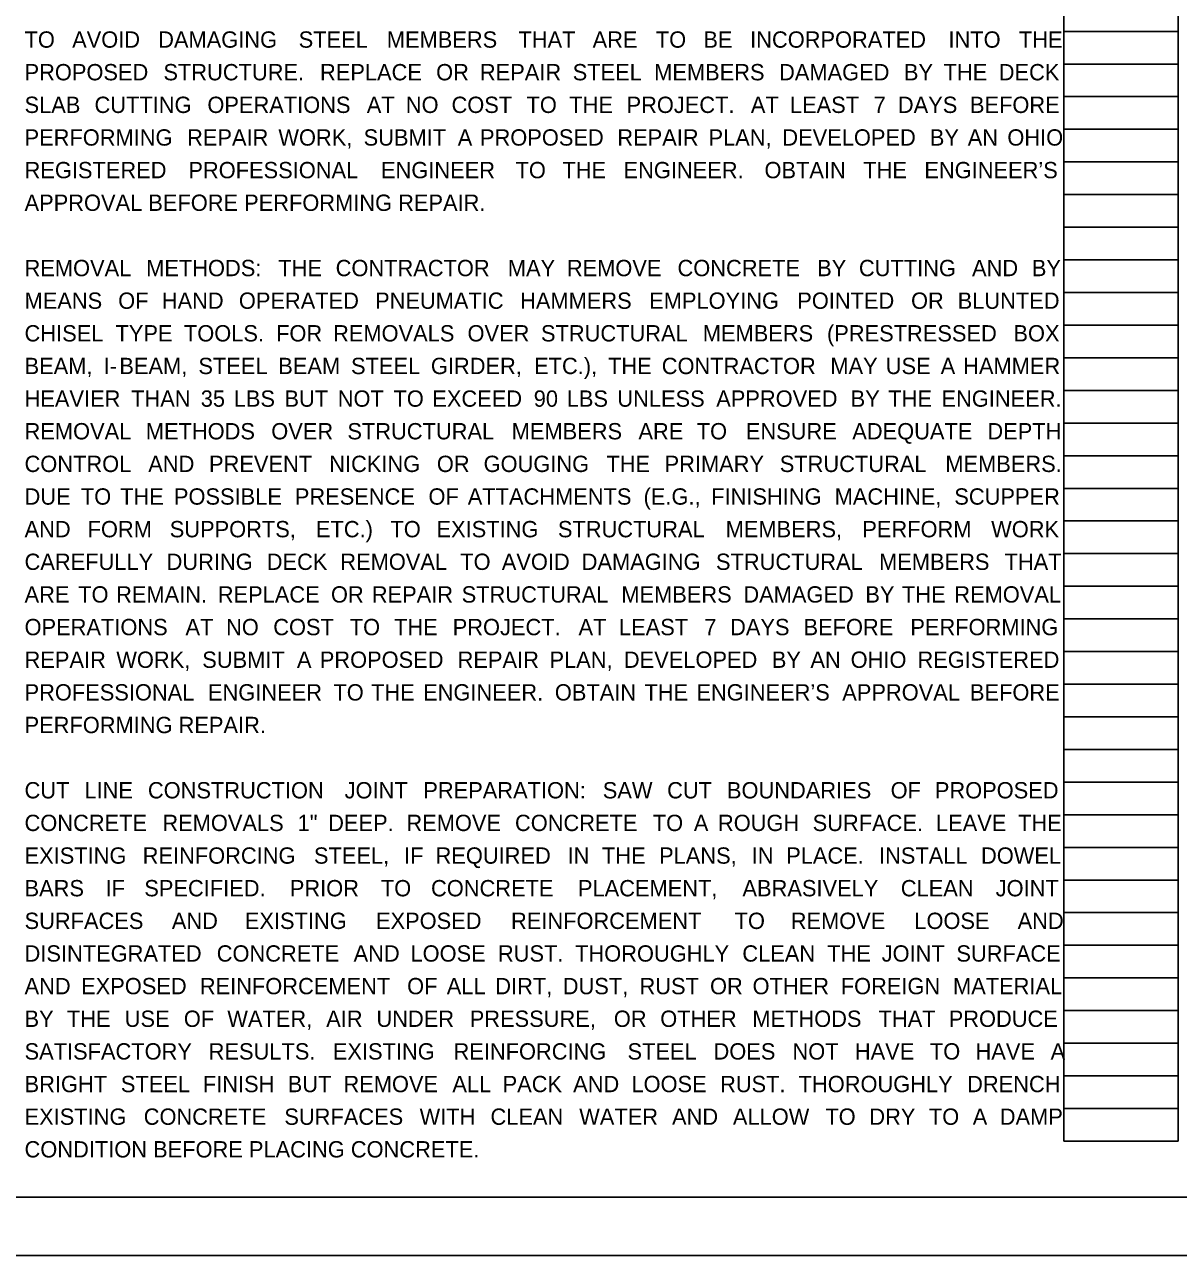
# Model space of a CAD drawing. Extents: x 0 to 34, y 0 to 22.
# Drawn here: x 12.29 to 22.19, y 0 to 10.56 of the extents above; entities that cross this region are included whole.
import ezdxf

# ---------------------------------------------------------------- set-up
doc = ezdxf.new("R2010")
doc.units = 0
for name, color, linetype in [('SC_Scratch1', 7, 'Continuous'), ('SH_Border', 7, 'Continuous'), ('SH_Cut_Line', 7, 'Continuous'), ('SH_Text', 7, 'Continuous')]:
    doc.layers.add(name, color=color, linetype=linetype)

msp = doc.modelspace()

# ---------------------------------------------------------------- linework, layer by layer
at = {"layer": 'SC_Scratch1'}
for p, q in [((21.207, 0.98), (21.207, 21.14)), ((22.187, 0.98), (22.187, 21.14)), ((21.207, 10.5), (22.187, 10.5)), ((21.207, 10.22), (22.187, 10.22)), ((21.207, 9.94), (22.187, 9.94)), ((21.207, 9.66), (22.187, 9.66)), ((21.207, 9.38), (22.187, 9.38)), ((21.207, 9.1), (22.187, 9.1)), ((21.207, 8.82), (22.187, 8.82)), ((21.207, 8.54), (22.187, 8.54)), ((21.207, 8.26), (22.187, 8.26)), ((21.207, 7.98), (22.187, 7.98)), ((21.207, 7.7), (22.187, 7.7)), ((21.207, 7.42), (22.187, 7.42)), ((21.207, 7.14), (22.187, 7.14)), ((21.207, 6.86), (22.187, 6.86)), ((21.207, 6.58), (22.187, 6.58)), ((21.207, 6.3), (22.187, 6.3)), ((21.207, 6.02), (22.187, 6.02)), ((21.207, 5.74), (22.187, 5.74)), ((21.207, 5.46), (22.187, 5.46)), ((21.207, 5.18), (22.187, 5.18)), ((21.207, 4.9), (22.187, 4.9)), ((21.207, 4.62), (22.187, 4.62)), ((21.207, 4.34), (22.187, 4.34)), ((21.207, 4.06), (22.187, 4.06)), ((21.207, 3.78), (22.187, 3.78)), ((21.207, 3.5), (22.187, 3.5)), ((21.207, 3.22), (22.187, 3.22)), ((21.207, 2.94), (22.187, 2.94)), ((21.207, 2.66), (22.187, 2.66)), ((21.207, 2.38), (22.187, 2.38)), ((21.207, 2.1), (22.187, 2.1)), ((21.207, 1.82), (22.187, 1.82)), ((21.207, 1.54), (22.187, 1.54)), ((21.207, 1.26), (22.187, 1.26)), ((21.207, 0.98), (22.187, 0.98))]:
    msp.add_line(p, q, dxfattribs=at)
msp.add_lwpolyline([(0, 22), (34, 22), (34, 0), (0, 0)], close=True, dxfattribs=at)
at = {"layer": 'SH_Border'}
msp.add_lwpolyline([(1.5, 21.5), (33.5, 21.5), (33.5, 0.5), (1.5, 0.5)], close=True, dxfattribs=at)
at = {"layer": 'SH_Cut_Line'}
msp.add_lwpolyline([(0, 0), (34, 0), (34, 22), (0, 22)], close=True, dxfattribs=at)

# ---------------------------------------------------------------- texts
at = {"layer": 'SH_Text'}
for s, p in [('TO ', (12.293, 10.36)), ('AVOID ', (12.701, 10.36)), ('DAMAGING ', (13.439, 10.36)), ('STEEL ', (14.644, 10.36)), ('MEMBERS ', (15.4, 10.36)), ('THAT ', (16.529, 10.36)), ('ARE ', (17.165, 10.36)), ('TO ', (17.707, 10.36)), ('BE ', (18.115, 10.36)), ('INCORPORATED ', (18.516, 10.36)), ('INTO ', (20.217, 10.36)), ('THE ', (20.821, 10.36)), ('PROPOSED ', (12.293, 10.08)), ('STRUCTURE. ', (13.484, 10.08)), ('REPLACE ', (14.827, 10.08)), ('OR ', (15.823, 10.08)), ('REPAIR ', (16.198, 10.08)), ('STEEL ', (16.994, 10.08)), ('MEMBERS ', (17.693, 10.08)), ('DAMAGED ', (18.764, 10.08)), ('BY ', (19.835, 10.08)), ('THE ', (20.175, 10.08)), ('DECK ', (20.648, 10.08)), ('SLAB ', (12.293, 9.8)), ('CUTTING ', (12.893, 9.8)), ('OPERATIONS ', (13.861, 9.8)), ('AT ', (15.228, 9.8)), ('NO ', (15.563, 9.8)), ('COST ', (15.955, 9.8)), ('TO ', (16.598, 9.8)), ('THE ', (16.965, 9.8)), ('PROJECT. ', (17.456, 9.8)), ('AT ', (18.522, 9.8)), ('LEAST ', (18.857, 9.8)), ('7 ', (19.575, 9.8)), ('DAYS ', (19.783, 9.8)), ('BEFORE ', (20.401, 9.8)), ('PERFORMING ', (12.293, 9.52)), ('REPAIR ', (13.687, 9.52)), ('WORK, ', (14.47, 9.52)), ('SUBMIT ', (15.201, 9.52)), ('A ', (16.008, 9.52)), ('PROPOSED ', (16.199, 9.52)), ('REPAIR ', (17.377, 9.52)), ('PLAN, ', (18.159, 9.52)), ('DEVELOPED ', (18.792, 9.52)), ('BY ', (20.057, 9.52)), ('AN ', (20.382, 9.52)), ('OHIO ', (20.722, 9.52)), ('REGISTERED ', (12.293, 9.24)), ('PROFESSIONAL ', (13.698, 9.24)), ('ENGINEER ', (15.35, 9.24)), ('TO ', (16.504, 9.24)), ('THE ', (16.906, 9.24)), ('ENGINEER. ', (17.43, 9.24)), ('OBTAIN ', (18.639, 9.24)), ('THE ', (19.486, 9.24)), ('ENGINEER’S ', (20.01, 9.24)), ('APPROVAL BEFORE PERFORMING REPAIR. ', (12.293, 8.96)), ('REMOVAL ', (12.293, 8.4)), ('METHODS: ', (13.336, 8.4)), ('THE ', (14.469, 8.4)), ('CONTRACTOR ', (14.961, 8.4)), ('MAY ', (16.438, 8.4)), ('REMOVE ', (16.944, 8.4)), ('CONCRETE ', (17.893, 8.4)), ('BY ', (19.091, 8.4)), ('CUTTING ', (19.449, 8.4)), ('AND ', (20.419, 8.4)), ('BY ', (20.932, 8.4)), ('MEANS ', (12.293, 8.12)), ('OF ', (13.096, 8.12)), ('HAND ', (13.47, 8.12)), ('OPERATED ', (14.131, 8.12)), ('PNEUMATIC ', (15.299, 8.12)), ('HAMMERS ', (16.543, 8.12)), ('EMPLOYING ', (17.65, 8.12)), ('POINTED ', (18.92, 8.12)), ('OR ', (19.896, 8.12)), ('BLUNTED ', (20.296, 8.12)), ('CHISEL ', (12.293, 7.84)), ('TYPE ', (13.073, 7.84)), ('TOOLS. ', (13.66, 7.84)), ('FOR ', (14.45, 7.84)), ('REMOVALS ', (14.939, 7.84)), ('OVER ', (16.092, 7.84)), ('STRUCTURAL ', (16.722, 7.84)), ('MEMBERS ', (18.11, 7.84)), ('(PRESTRESSED ', (19.175, 7.84)), ('BOX ', (20.774, 7.84)), ('ETC.), ', (16.663, 7.56)), ('BEAM, ', (12.293, 7.56)), ('I-', (12.971, 7.56)), ('BEAM, ', (13.106, 7.56)), ('STEEL ', (13.784, 7.56)), ('BEAM ', (14.469, 7.56)), ('STEEL ', (15.093, 7.56)), ('GIRDER, ', (15.778, 7.56)), ('THE ', (17.297, 7.56)), ('CONTRACTOR ', (17.758, 7.56)), ('MAY ', (19.204, 7.56)), ('USE ', (19.679, 7.56)), ('A ', (20.15, 7.56)), ('HAMMER ', (20.343, 7.56)), ('HEAVIER ', (12.293, 7.28)), ('THAN ', (13.207, 7.28)), ('35 ', (13.804, 7.28)), ('LBS ', (14.087, 7.28)), ('BUT ', (14.522, 7.28)), ('NOT ', (14.979, 7.28)), ('TO ', (15.457, 7.28)), ('EXCEED ', (15.79, 7.28)), ('90 ', (16.66, 7.28)), ('LBS ', (16.943, 7.28)), ('UNLESS ', (17.377, 7.28)), ('APPROVED ', (18.225, 7.28)), ('BY ', (19.378, 7.28)), ('THE ', (19.701, 7.28)), ('ENGINEER. ', (20.157, 7.28)), ('REMOVAL ', (12.293, 7)), ('METHODS ', (13.333, 7)), ('OVER ', (14.409, 7)), ('STRUCTURAL ', (15.062, 7)), ('MEMBERS ', (16.471, 7)), ('ARE ', (17.558, 7)), ('TO  ', (18.058, 7)), ('ENSURE ', (18.479, 7)), ('ADEQUATE ', (19.392, 7)), ('DEPTH ', (20.551, 7)), ('CONTROL ', (12.293, 6.72)), ('AND ', (13.354, 6.72)), ('PREVENT ', (13.875, 6.72)), ('NICKING ', (14.906, 6.72)), ('OR ', (15.829, 6.72)), ('GOUGING ', (16.23, 6.72)), ('THE ', (17.283, 6.72)), ('PRIMARY ', (17.782, 6.72)), ('STRUCTURAL ', (18.77, 6.72)), ('MEMBERS. ', (20.19, 6.72)), ('DUE ', (12.293, 6.44)), ('TO ', (12.776, 6.44)), ('THE ', (13.113, 6.44)), ('POSSIBLE ', (13.574, 6.44)), ('PRESENCE ', (14.611, 6.44)), ('OF ', (15.757, 6.44)), ('ATTACHMENTS ', (16.094, 6.44)), ('(E.G., ', (17.602, 6.44)), ('FINISHING ', (18.182, 6.44)), ('MACHINE, ', (19.241, 6.44)), ('SCUPPER ', (20.267, 6.44)), ('AND ', (12.293, 6.16)), ('FORM ', (12.834, 6.16)), ('SUPPORTS, ', (13.538, 6.16)), ('ETC.) ', (14.792, 6.16)), ('TO ', (15.431, 6.16)), ('EXISTING ', (15.826, 6.16)), ('STRUCTURAL ', (16.867, 6.16)), ('MEMBERS, ', (18.306, 6.16)), ('PERFORM ', (19.478, 6.16)), ('WORK ', (20.583, 6.16)), ('CAREFULLY ', (12.293, 5.88)), ('DURING ', (13.511, 5.88)), ('DECK ', (14.37, 5.88)), ('REMOVAL ', (15.001, 5.88)), ('TO ', (16.03, 5.88)), ('AVOID ', (16.386, 5.88)), ('DAMAGING ', (17.071, 5.88)), ('STRUCTURAL ', (18.223, 5.88)), ('MEMBERS ', (19.622, 5.88)), ('THAT ', (20.698, 5.88)), ('ARE ', (12.293, 5.6)), ('TO ', (12.753, 5.6)), ('REMAIN. ', (13.078, 5.6)), ('REPLACE ', (13.95, 5.6)), ('OR ', (14.921, 5.6)), ('REPAIR ', (15.271, 5.6)), ('STRUCTURAL ', (16.042, 5.6)), ('MEMBERS ', (17.411, 5.6)), ('DAMAGED ', (18.458, 5.6)), ('BY ', (19.504, 5.6)), ('THE ', (19.818, 5.6)), ('REMOVAL ', (20.267, 5.6)), ('OPERATIONS ', (12.293, 5.32)), ('AT ', (13.673, 5.32)), ('NO ', (14.021, 5.32)), ('COST ', (14.426, 5.32)), ('TO ', (15.082, 5.32)), ('THE ', (15.462, 5.32)), ('PROJECT. ', (15.965, 5.32)), ('AT ', (17.044, 5.32)), ('LEAST ', (17.391, 5.32)), ('7 ', (18.123, 5.32)), ('DAYS ', (18.344, 5.32)), ('BEFORE ', (18.974, 5.32)), ('PERFORMING ', (19.89, 5.32)), ('REPAIR ', (12.293, 5.04)), ('WORK, ', (13.08, 5.04)), ('SUBMIT ', (13.817, 5.04)), ('A ', (14.629, 5.04)), ('PROPOSED ', (14.825, 5.04)), ('REPAIR ', (16.007, 5.04)), ('PLAN, ', (16.795, 5.04)), ('DEVELOPED ', (17.433, 5.04)), ('BY ', (18.702, 5.04)), ('AN ', (19.033, 5.04)), ('OHIO ', (19.378, 5.04)), ('REGISTERED ', (19.951, 5.04)), ('PROFESSIONAL ', (12.293, 4.76)), ('ENGINEER ', (13.866, 4.76)), ('TO ', (14.942, 4.76)), ('THE ', (15.265, 4.76)), ('ENGINEER. ', (15.711, 4.76)), ('OBTAIN ', (16.841, 4.76)), ('THE ', (17.61, 4.76)), ('ENGINEER’S ', (18.055, 4.76)), ('APPROVAL ', (19.306, 4.76)), ('BEFORE ', (20.401, 4.76)), ('PERFORMING REPAIR. ', (12.293, 4.48)), ('CUT ', (12.293, 3.92)), ('LINE ', (12.806, 3.92)), ('CONSTRUCTION ', (13.351, 3.92)), ('JOINT ', (15.038, 3.92)), ('PREPARATION: ', (15.713, 3.92)), ('SAW ', (17.252, 3.92)), ('CUT ', (17.804, 3.92)), ('BOUNDARIES ', (18.317, 3.92)), ('OF ', (19.721, 3.92)), ('PROPOSED ', (20.1, 3.92)), ('CONCRETE ', (12.293, 3.64)), ('REMOVALS ', (13.475, 3.64)), ('1" ', (14.635, 3.64)), ('DEEP. ', (14.897, 3.64)), ('REMOVE ', (15.568, 3.64)), ('CONCRETE ', (16.499, 3.64)), ('TO ', (17.681, 3.64)), ('A ', (18.033, 3.64)), ('ROUGH ', (18.24, 3.64)), ('SURFACE. ', (19.052, 3.64)), ('LEAVE ', (20.11, 3.64)), ('THE ', (20.814, 3.64)), ('EXISTING ', (12.293, 3.36)), ('REINFORCING ', (13.306, 3.36)), ('STEEL, ', (14.775, 3.36)), ('IF ', (15.548, 3.36)), ('REQUIRED ', (15.818, 3.36)), ('IN ', (16.95, 3.36)), ('THE ', (17.245, 3.36)), ('PLANS, ', (17.735, 3.36)), ('IN ', (18.53, 3.36)), ('PLACE. ', (18.825, 3.36)), ('INSTALL ', (19.621, 3.36)), ('DOWEL ', (20.496, 3.36)), ('BARS ', (12.293, 3.08)), ('IF ', (12.988, 3.08)), ('SPECIFIED. ', (13.32, 3.08)), ('PRIOR ', (14.568, 3.08)), ('TO ', (15.349, 3.08)), ('CONCRETE ', (15.779, 3.08)), ('PLACEMENT, ', (17.039, 3.08)), ('ABRASIVELY ', (18.45, 3.08)), ('CLEAN ', (19.808, 3.08)), ('JOINT ', (20.622, 3.08)), ('SURFACES ', (12.293, 2.8)), ('AND ', (13.556, 2.8)), ('EXISTING ', (14.182, 2.8)), ('EXPOSED ', (15.307, 2.8)), ('REINFORCEMENT ', (16.465, 2.8)), ('TO ', (18.383, 2.8)), ('REMOVE ', (18.864, 2.8)), ('LOOSE ', (19.924, 2.8)), ('AND ', (20.81, 2.8)), ('DISINTEGRATED ', (12.293, 2.52)), ('CONCRETE ', (13.941, 2.52)), ('AND ', (15.115, 2.52)), ('LOOSE ', (15.603, 2.52)), ('RUST. ', (16.353, 2.52)), ('THOROUGHLY ', (17.015, 2.52)), ('CLEAN ', (18.449, 2.52)), ('THE ', (19.177, 2.52)), ('JOINT ', (19.644, 2.52)), ('SURFACE ', (20.285, 2.52)), ('AND ', (12.293, 2.24)), ('EXPOSED ', (12.778, 2.24)), ('REINFORCEMENT ', (13.796, 2.24)), ('OF ', (15.574, 2.24)), ('ALL ', (15.914, 2.24)), ('DIRT, ', (16.33, 2.24)), ('DUST, ', (16.909, 2.24)), ('RUST ', (17.567, 2.24)), ('OR ', (18.172, 2.24)), ('OTHER ', (18.537, 2.24)), ('FOREIGN ', (19.293, 2.24)), ('MATERIAL ', (20.256, 2.24)), ('BY ', (12.293, 1.96)), ('THE ', (12.656, 1.96)), ('USE ', (13.152, 1.96)), ('OF ', (13.659, 1.96)), ('WATER, ', (14.032, 1.96)), ('AIR ', (14.88, 1.96)), ('UNDER ', (15.311, 1.96)), ('PRESSURE, ', (16.111, 1.96)), ('OR ', (17.347, 1.96)), ('OTHER ', (17.745, 1.96)), ('METHODS ', (18.535, 1.96)), ('THAT ', (19.618, 1.96)), ('PRODUCE ', (20.219, 1.96)), ('SATISFACTORY ', (12.293, 1.68)), ('RESULTS. ', (13.872, 1.68)), ('EXISTING ', (14.937, 1.68)), ('REINFORCING ', (15.972, 1.68)), ('STEEL ', (17.464, 1.68)), ('DOES ', (18.202, 1.68)), ('NOT ', (18.879, 1.68)), ('HAVE ', (19.414, 1.68)), ('TO ', (20.058, 1.68)), ('HAVE ', (20.449, 1.68)), ('A ', (21.093, 1.68)), ('BRIGHT ', (12.293, 1.4)), ('STEEL ', (13.119, 1.4)), ('FINISH ', (13.822, 1.4)), ('BUT ', (14.55, 1.4)), ('REMOVE ', (15.028, 1.4)), ('ALL ', (15.962, 1.4)), ('PACK ', (16.393, 1.4)), ('AND ', (16.998, 1.4)), ('LOOSE ', (17.498, 1.4)), ('RUST. ', (18.258, 1.4)), ('THOROUGHLY ', (18.932, 1.4)), ('DRENCH ', (20.377, 1.4)), ('EXISTING ', (12.293, 1.12)), ('CONCRETE ', (13.315, 1.12)), ('SURFACES ', (14.521, 1.12)), ('WITH ', (15.681, 1.12)), ('CLEAN ', (16.289, 1.12)), ('WATER ', (17.05, 1.12)), ('AND ', (17.846, 1.12)), ('ALLOW ', (18.368, 1.12)), ('TO ', (19.161, 1.12)), ('DRY ', (19.538, 1.12)), ('TO ', (20.049, 1.12)), ('A ', (20.425, 1.12)), ('DAMP ', (20.657, 1.12)), ('CONDITION BEFORE PLACING CONCRETE. ', (12.293, 0.84))]:
    msp.add_text(s, height=0.14, dxfattribs=at).set_placement(p)

doc.saveas('drawing.dxf')
